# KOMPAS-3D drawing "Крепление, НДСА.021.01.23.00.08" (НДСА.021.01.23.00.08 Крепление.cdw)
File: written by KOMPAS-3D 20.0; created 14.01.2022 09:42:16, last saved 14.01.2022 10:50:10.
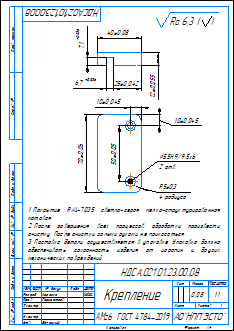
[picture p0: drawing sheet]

Sheet 1: A4, portrait

Document properties: Знак неуказанной шероховатости: 4; Параметр неуказанной шероховатости: Ra 6,3; Полное имя файла: НДСА.021.01.23.00.08 Крепление.m3d; PLM_CDWXDTO: <item xmlns="http://appius.ru/pdm" xmlns:xs="http://www.w3.org/2001/XMLSchema" xmlns:xsi="http://www.w3.org/2001/XMLSchema-instance" xsi:type="item">  <element xmlns:d2p1="http://v8.1c.ru/8.1/data/enterprise/current-config" xsi:type="d2p1:CatalogRef.aps_Элемен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; Масса: 0.076235; PDM_DOCXDTO: <item xmlns="http://appius.ru/pdm" xmlns:xs="http://www.w3.org/2001/XMLSchema" xmlns:xsi="http://www.w3.org/2001/XMLSchema-instance" xsi:type="item">  <element xmlns:d2p1="http://v8.1c.ru/8.1/data/enterprise/current-config" xsi:type="d2p1:CatalogRef.aps_Элемен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; PDM_ITEMXDTO: <item xmlns="http://appius.ru/pdm" xmlns:xs="http://www.w3.org/2001/XMLSchema" xmlns:xsi="http://www.w3.org/2001/XMLSchema-instance" xsi:type="item">  <element xmlns:d2p1="http://v8.1c.ru/8.1/data/enterprise/current-config" xsi:type="d2p1:CatalogRef.aps_Элемен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

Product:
- Part/product: Крепление  | designation НДСА.021.01.23.00.08
    Материал: АМг6  ГОСТ 4784-2019 (density 2640 kg/m3)
    Масса: 0.076235
    additional columns: <item xmlns="http://appius.ru/pdm" xmlns:xs="http://www.w3.org/2001/XMLSchema" x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; <item xmlns="http://appius.ru/pdm" xmlns:xs="http://www.w3.org/2001/XMLSchema" x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
    source file: НДСА.021.01.23.00.08 Крепление.cdw

Title block, sheet 1: Наименование: Крепление; designation: НДСА.021.01.23.00.08; Материал: АМг6  ГОСТ 4784-2019; Масса: 0,08; Количество листов документа: 1; organisation: АО"НПП"ЭСТО"; Форматы листов документа: A4; stored path: C:\Users\korychko\Desktop\PLM\НДСА.021.01.23.00.08 Крепление.cdw; Разработал: Корячко; Проверил: Горностаев; Утвердил: Белецкий; Разработал, date: 14.01.2022

Views: Проекционный вид 2, Проекционный вид 3
Referenced files in C:\Users\korychko\Desktop\PLM\: НДСА.021.01.23.00.08 Крепление.m3d
Referenced files in C:\Users\gornostaev\Desktop\PLM\: НДСА.021.01.23.00.08 Крепление.m3d
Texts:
  JS10
  JS11
  Ra 6,3
  Ra 6,3 ( )
  НДСА.021.01.23.00.08 Крепление
Dimensions and other numbers on the sheet: 70±0,06; 2 отв.; 50±0,05; 10±0,045; 5; 4 радиуса; 40±0,08; 12±0,055; 7,1; 25±0,042; 6,7; 1:1; 1; 0,08; 14.01.2022

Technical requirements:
  Покрытие RAL-7035 светло-серая мелко-структурированная
  матовая.
  После завершения всех процессов обработки произвести
  очистку. После очистки голыми руками не прикасаться.
  Поставка детали осуществляется в упаковке. Упаковка должна
  обеспечивать сохранность изделия от царапин и других
  механических повреждений.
